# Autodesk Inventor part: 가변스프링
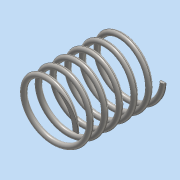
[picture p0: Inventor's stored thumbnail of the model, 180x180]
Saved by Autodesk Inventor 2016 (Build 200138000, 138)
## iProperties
Created: 2018-11
Part Number: 가변스프링
Material: 스테인레스 스틸
Document SubType Name: Modeling
Designer: user
Density: 8 g/cm^3
Appearance: 반연마
Mass: 84.1963 g
Surface Area: 106.449 cm^2
Volume: 10.5245 cm^3
Author: user
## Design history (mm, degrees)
sketch "스케치1"
  geometry: L1 (0, 0)-(22.5, 0); L2 (22.5, 0)-(22.5, 67.25); L3 (22.5, 67.25)-(0, 67.25); L4 (0, 67.25)-(0, 0); C1 r 2 at (22.5, 0)
  constraints: 8 end point, 2 parallel, 1 centre point, 1 coincident, 1 horizontal, 1 perpendicular
  dimensions: "d0" = 67.25 distance between parallel lines of L1 L3 (derived); "d1" = 45 diameter of L2 L4; "d2" = 4 diameter of C1
feature "코일1" sketch "스케치1" pitch "d3" = 10; turns "d5" = 6; dims "d4" = 67.25 (= d0), "d6" = 0, angle "d7" = 90 deg, angle "d8" = 90 deg, "d9" = 0, "d10" = 0
sketch "스케치2"
  geometry: L1 (0, 30)-(67.25, 30); L2 (67.25, 30)-(67.25, -30); L3 (67.25, -30)-(0, -30); L4 (0, -30)-(0, 30); 2 further points
  constraints: 8 end point, 2 parallel, 1 coincident, 1 horizontal, 1 midpoint, 1 perpendicular
  dimensions: "d11" = 67.25 distance between parallel lines of L4 L2 (= d0); "d12" = 60 distance between parallel lines of L3 L1
extrude "돌출1" sketch "스케치2" stored distance "d13" = 100; taper "d14" = 0 deg
node "솔리드1"
